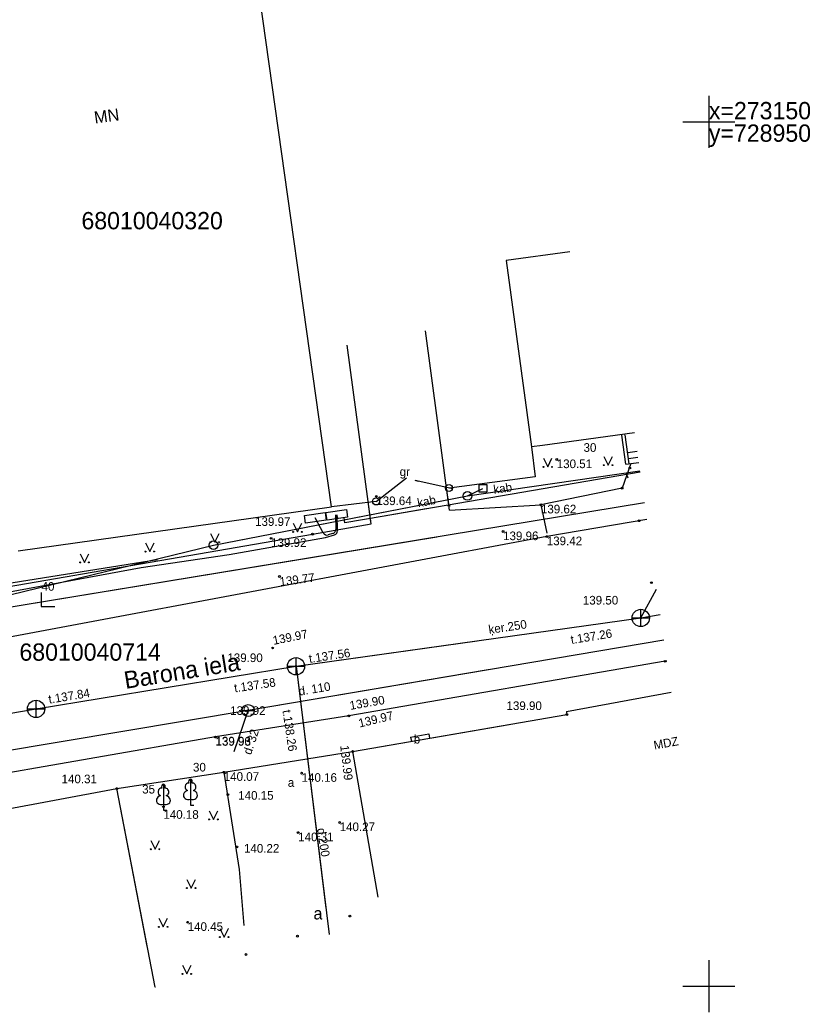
# Model space of a CAD drawing. Extents: x 728848 to 728956, y 273098 to 273185.
# Drawn here: x 728910.1 to 728955.9, y 273098.5 to 273155.9 of the extents above; entities that cross this region are included whole.
import ezdxf

# ---------------------------------------------------------------- set-up
doc = ezdxf.new("R2010")
doc.units = 0
for name, color, linetype in [('BUVE_BDET_####_####_#', 7, 'Continuous'), ('BUVE_BDET_####_TKST_#', 7, 'Continuous'), ('BUVE_EKAS_####_####_#', 7, 'Continuous'), ('BUVE_EKAS_RAKS_TKST_#', 7, 'Continuous'), ('CELI_CAPM_####_####_#', 7, 'Continuous'), ('CELI_CMAL_####_####_#', 7, 'Continuous'), ('CELI_CSEG_####_TKST_#', 7, 'Continuous'), ('CELI_IELA_####_TKST_#', 7, 'Continuous'), ('CELI_SEGL_####_####_#', 7, 'Continuous'), ('ELEK_ELEM_####_####_#', 7, 'Continuous'), ('ELEK_VADP_ZSPR_####_#', 7, 'Continuous'), ('ELEK_VADP_ZSPR_####_I', 7, 'Continuous'), ('ELEK_VADV_ZSPR_####_#', 7, 'Continuous'), ('ELEK_VADV_ZSPR_TKST_#', 7, 'Continuous'), ('GEOD_ELEM_####_####_#', 7, 'Continuous'), ('GEOD_KORD_####_TKST_#', 7, 'Continuous'), ('Level 1', 7, 'Continuous'), ('Level 23', 7, 'Continuous'), ('NORB_ELEM_####_####_#', 7, 'Continuous'), ('NORB_ZOGS_BARJ_####_#', 7, 'Continuous'), ('NORB_ZOGS_KOKA_####_#', 7, 'Continuous'), ('RELJ_AATZ_####_TKST_#', 7, 'Continuous'), ('RELJ_ELEM_####_####_#', 7, 'Continuous'), ('ROBZ_KADS_####_TKST_#', 7, 'Continuous'), ('ROBZ_UZMR_####_####_#', 7, 'Continuous'), ('SAKK_KKAN_####_####_#', 7, 'Continuous'), ('SKAN_ELEM_####_####_#', 7, 'Continuous'), ('SKAN_VADP_PAST_####_#', 7, 'Continuous'), ('SKAN_VADP_PAST_TKST_#', 7, 'Continuous'), ('TERT_ELEM_####_####_#', 7, 'Continuous'), ('UDTK_ELEM_####_####_#', 7, 'Continuous'), ('UDTK_ELEM_####_TKST_#', 7, 'Continuous'), ('UDTK_VADP_UDEN_####_#', 7, 'Continuous'), ('UDTK_VADP_UDEN_TKST_#', 7, 'Continuous')]:
    doc.layers.add(name, color=color, linetype=linetype)

msp = doc.modelspace()

# ---------------------------------------------------------------- linework, layer by layer
at = {"layer": 'BUVE_BDET_####_####_#'}
for p, q in [((728945.201, 273130.202), (728944.965, 273131.873)), ((728945.391, 273130.228), (728945.156, 273131.897)), ((728945.301, 273130.87), (728945.849, 273130.946)), ((728945.349, 273130.528), (728945.897, 273130.604)), ((728945.201, 273130.202), (728945.939, 273130.304)), ((728932.744, 273114.398), (728933.793, 273114.592)), ((728932.744, 273114.398), (728932.787, 273114.164)), ((728933.793, 273114.592), (728933.839, 273114.345))]:
    msp.add_line(p, q, dxfattribs=at)
at = {"layer": 'BUVE_EKAS_####_####_#'}
for p, q in [((728928.159, 273127.726), (728923.879, 273158.199)), ((728941.955, 273142.483), (728938.276, 273141.982)), ((728938.276, 273141.982), (728939.731, 273131.201)), ((728945.697, 273132.02), (728940.375, 273131.284)), ((728940.375, 273131.284), (728939.731, 273131.201)), ((728910.037, 273125.181), (728928.159, 273127.726)), ((728941.754, 273115.883), (728947.818, 273117.013)), ((728929.388, 273113.579), (728941.786, 273115.713)), ((728941.754, 273115.883), (728941.786, 273115.713)), ((728929.388, 273113.579), (728938.449, 273115.139)), ((728929.388, 273113.579), (728930.84, 273105.143)), ((728899.988, 273108.511), (728915.742, 273111.435)), ((728917.962, 273099.938), (728915.742, 273111.435)), ((728917.502, 273102.322), (728915.742, 273111.435))]:
    msp.add_line(p, q, dxfattribs=at)
at = {"layer": 'CELI_CAPM_####_####_#'}
msp.add_line((728947.564, 273118.811), (728947.473, 273118.795), dxfattribs=at)
for points in [[(728946.407, 273126.997), (728940.62, 273126.01)], [(728947.473, 273118.795), (728929.173, 273115.635), (728921.451, 273114.43)], [(728921.451, 273114.43), (728906.807, 273111.886), (728887.177, 273108.316), (728884.836, 273107.893)]]:
    msp.add_lwpolyline(points, dxfattribs=at)
at = {"layer": 'CELI_CMAL_####_####_#'}
for p, q in [((728934.999, 273127.535), (728933.598, 273137.914)), ((728930.461, 273126.743), (728929.065, 273137.091)), ((728934.964, 273127.794), (728934.862, 273128.552)), ((728930.444, 273126.872), (728930.308, 273127.882)), ((728905.649, 273122.465), (728927.067, 273126.15))]:
    msp.add_line(p, q, dxfattribs=at)
for points in [[(728945.475, 273130.229), (728944.976, 273128.81)], [(728945.222, 273129.688), (728945.313, 273129.411)], [(728944.976, 273128.81), (728940.282, 273127.851), (728940.62, 273126.21)], [(728934.999, 273127.535), (728940.282, 273127.851)], [(728927.067, 273126.15), (728930.461, 273126.743)], [(728940.62, 273126.01), (728905.191, 273119.377), (728883.236, 273115.671)], [(728915.742, 273111.435), (728921.935, 273112.38)], [(728921.935, 273112.38), (728922.812, 273106.757), (728923.087, 273103.503)]]:
    msp.add_lwpolyline(points, dxfattribs=at)
at = {"layer": 'CELI_SEGL_####_####_#'}
msp.add_lwpolyline([(728921.935, 273112.38), (728921.929, 273112.38), (728929.388, 273113.579)], dxfattribs=at)
at = {"layer": 'ELEK_ELEM_####_####_#'}
for points in [[(728937.145, 273128.578), (728936.699, 273128.578), (728936.699, 273129.018), (728937.145, 273129.018)], [(728927.838, 273127.406), (728929.025, 273127.586), (728929.092, 273127.141), (728927.906, 273126.961)], [(728926.603, 273127.239), (728927.793, 273127.398), (728927.853, 273126.952), (728926.663, 273126.793)]]:
    msp.add_lwpolyline(points, close=True, dxfattribs=at)
for centre in [(728936.036, 273128.36), (728921.335, 273125.511)]:
    msp.add_circle(centre, 0.25, dxfattribs=at)
at = {"layer": 'ELEK_VADP_ZSPR_####_#'}
for points in [[(728946.018, 273129.745), (728931.098, 273127.179), (728928.944, 273126.808), (728928.895, 273127.096)], [(728936.036, 273128.36), (728936.922, 273128.797)], [(728933.644, 273127.617), (728931.098, 273127.179), (728928.944, 273126.808), (728928.895, 273127.096)]]:
    msp.add_lwpolyline(points, dxfattribs=at)
at = {"layer": 'ELEK_VADP_ZSPR_####_I'}
for p, q in [((728928.389, 273127.266), (728928.409, 273126.427)), ((728928.511, 273126.353), (728928.489, 273127.268)), ((728928.511, 273126.353), (728928.489, 273127.268)), ((728927.817, 273125.955), (728928.332, 273126.107)), ((728927.817, 273125.955), (728928.332, 273126.107)), ((728928.23, 273126.181), (728927.976, 273126.106))]:
    msp.add_line(p, q, dxfattribs=at)
for points in [[(728927.684, 273126.23), (728927.228, 273127.096)], [(728882.763, 273118.325), (728887.201, 273119.02), (728893.506, 273120.092), (728901.17, 273121.265), (728917.144, 273124.228), (728922.252, 273124.972), (728927.817, 273125.955)], [(728884.14, 273118.541), (728887.201, 273119.02), (728893.506, 273120.092), (728901.17, 273121.265), (728917.144, 273124.228), (728922.252, 273124.972), (728927.817, 273125.955)]]:
    msp.add_lwpolyline(points, dxfattribs=at)
for centre, start, end in [((728928.159, 273126.421), 286.45134, 1.36735), ((728928.261, 273126.347), 286.45134, 1.36735), ((728928.261, 273126.347), 286.45134, 1.36735), ((728927.905, 273126.346), 207.75459, 286.45134)]:
    msp.add_arc(centre, 0.25, start, end, dxfattribs=at)
at = {"layer": 'ELEK_VADV_ZSPR_####_#'}
for p, q in [((728936.036, 273128.36), (728946.01, 273129.807)), ((728921.335, 273125.511), (728936.036, 273128.36)), ((728921.335, 273125.511), (728933.544, 273127.877)), ((728894.302, 273118.95), (728921.335, 273125.511))]:
    msp.add_line(p, q, dxfattribs=at)
at = {"layer": 'GEOD_ELEM_####_####_#'}
for p, q in [((728950, 273151.5), (728950, 273150)), ((728948.5, 273150), (728950, 273150)), ((728950, 273150), (728950, 273148.5)), ((728950, 273150), (728951.5, 273150)), ((728950, 273101.5), (728950, 273100)), ((728948.5, 273100), (728950, 273100)), ((728950, 273100), (728950, 273098.5)), ((728950, 273100), (728951.5, 273100))]:
    msp.add_line(p, q, dxfattribs=at)
at = {"layer": 'Level 1'}
for p, q in [((728911.357, 273122.769), (728911.357, 273121.969)), ((728911.357, 273121.969), (728912.157, 273121.969))]:
    msp.add_line(p, q, dxfattribs=at)
at = {"layer": 'Level 23'}
for p, q in [((728940.422, 273130.543), (728940.672, 273130.043)), ((728940.672, 273130.043), (728940.922, 273130.543)), ((728943.917, 273130.642), (728944.167, 273130.142)), ((728944.167, 273130.142), (728944.417, 273130.642))]:
    msp.add_line(p, q, dxfattribs=at)
for centre, radius in [((728940.422, 273130.042), 0.028), ((728940.922, 273130.042), 0.0263), ((728943.916, 273130.142), 0.028), ((728944.416, 273130.142), 0.0263)]:
    msp.add_circle(centre, radius, dxfattribs=at)
at = {"layer": 'NORB_ELEM_####_####_#'}
for centre in [(728934.964, 273128.82), (728930.745, 273128.042)]:
    msp.add_circle(centre, 0.202, dxfattribs=at)
at = {"layer": 'NORB_ZOGS_BARJ_####_#'}
for points in [[(728930.745, 273128.042), (728932.505, 273129.41)], [(728935.188, 273128.772), (728933.01, 273129.246)], [(728933.199, 273129.205), (728933.01, 273129.246)]]:
    msp.add_lwpolyline(points, dxfattribs=at)
at = {"layer": 'NORB_ZOGS_KOKA_####_#'}
msp.add_line((728930.745, 273128.042), (728928.159, 273127.726), dxfattribs=at)
msp.add_lwpolyline([(728939.731, 273131.201), (728939.949, 273129.466), (728934.964, 273128.82)], dxfattribs=at)
at = {"layer": 'RELJ_ELEM_####_####_#'}
for centre in [(728941.197, 273130.47), (728945.427, 273129.976), (728944.976, 273128.81), (728930.758, 273128.331), (728934.964, 273127.794), (728940.282, 273127.851), (728928.453, 273127.128), (728945.971, 273126.926), (728938.092, 273126.303), (728924.669, 273125.911), (728927.067, 273126.15), (728940.62, 273126.01), (728925.156, 273123.7), (728946.674, 273123.345), (728946.06, 273121.302), (728924.758, 273119.566), (728926.111, 273118.506), (728947.473, 273118.795), (728911.07, 273116.044), (728923.344, 273115.945), (728929.173, 273115.635), (728941.786, 273115.713), (728921.457, 273114.41), (728929.388, 273113.579), (728921.929, 273112.38), (728926.435, 273112.324), (728915.742, 273111.435), (728922.17, 273111.086), (728918.437, 273110.385), (728928.637, 273109.471), (728926.237, 273108.887), (728922.695, 273108.059), (728929.224, 273104.056), (728919.844, 273103.7), (728926.193, 273102.894), (728923.217, 273101.834)]:
    msp.add_circle(centre, 0.05, dxfattribs=at)
at = {"layer": 'ROBZ_UZMR_####_####_#'}
msp.add_lwpolyline([(728906.58, 273122.86), (728918.09, 273124.69)], dxfattribs=at)
at = {"layer": 'SAKK_KKAN_####_####_#'}
for points in [[(728882.864, 273117.761), (728887.446, 273118.532), (728897.906, 273120.141), (728908.778, 273121.814), (728946.269, 273127.973)], [(728884.177, 273117.982), (728887.446, 273118.532), (728897.906, 273120.141), (728908.778, 273121.814), (728934.266, 273126.001)]]:
    msp.add_lwpolyline(points, dxfattribs=at)
at = {"layer": 'SKAN_ELEM_####_####_#'}
for p, q in [((728946.06, 273120.802), (728946.06, 273121.802)), ((728945.56, 273121.302), (728946.56, 273121.302)), ((728926.111, 273118.006), (728926.111, 273119.006)), ((728925.611, 273118.506), (728926.611, 273118.506)), ((728910.57, 273116.044), (728911.57, 273116.044)), ((728911.07, 273115.544), (728911.07, 273116.544))]:
    msp.add_line(p, q, dxfattribs=at)
for centre in [(728946.06, 273121.302), (728926.111, 273118.506), (728911.07, 273116.044)]:
    msp.add_circle(centre, 0.5, dxfattribs=at)
at = {"layer": 'SKAN_VADP_PAST_####_#'}
for points in [[(728946.06, 273121.302), (728946.977, 273122.962)], [(728926.111, 273118.506), (728946.06, 273121.302), (728947.184, 273121.501)], [(728926.111, 273118.506), (728936.587, 273119.974)], [(728886.872, 273111.928), (728911.07, 273116.044), (728926.111, 273118.506), (728928.031, 273102.999)], [(728886.872, 273111.928), (728911.07, 273116.044), (728926.111, 273118.506), (728927.844, 273104.509)], [(728917.987, 273099.945), (728917.961, 273099.941)]]:
    msp.add_lwpolyline(points, dxfattribs=at)
at = {"layer": 'TERT_ELEM_####_####_#'}
for p, q in [((728925.943, 273126.781), (728926.193, 273126.281)), ((728926.193, 273126.281), (728926.443, 273126.781)), ((728921.159, 273126.188), (728921.409, 273125.688)), ((728921.409, 273125.688), (728921.659, 273126.188)), ((728917.397, 273125.646), (728917.647, 273125.146)), ((728917.647, 273125.146), (728917.897, 273125.646)), ((728913.624, 273125.017), (728913.874, 273124.517)), ((728913.874, 273124.517), (728914.124, 273125.017)), ((728918.437, 273110.532), (728918.437, 273110.185)), ((728920.004, 273110.828), (728920.004, 273110.481)), ((728920.004, 273110.481), (728920.204, 273110.481)), ((728918.437, 273110.185), (728918.637, 273110.185)), ((728921.084, 273110.152), (728921.334, 273109.652)), ((728921.334, 273109.652), (728921.584, 273110.152)), ((728917.703, 273108.423), (728917.953, 273107.923)), ((728917.953, 273107.923), (728918.203, 273108.423)), ((728919.798, 273106.179), (728920.048, 273105.679)), ((728920.048, 273105.679), (728920.298, 273106.179)), ((728918.18, 273103.934), (728918.43, 273103.434)), ((728918.43, 273103.434), (728918.68, 273103.934)), ((728921.709, 273103.346), (728921.959, 273102.846)), ((728921.709, 273103.346), (728921.77, 273103.224)), ((728921.959, 273102.846), (728922.209, 273103.346)), ((728922.193, 273103.314), (728922.209, 273103.346)), ((728919.54, 273101.212), (728919.79, 273100.712)), ((728919.79, 273100.712), (728920.04, 273101.212))]:
    msp.add_line(p, q, dxfattribs=at)
for points in [[(728918.437, 273111.685), (728918.437, 273110.532)], [(728918.527, 273111.453), (728918.526, 273111.454)], [(728920.004, 273111.981), (728920.004, 273110.828)], [(728920.094, 273111.749), (728920.093, 273111.75)]]:
    msp.add_lwpolyline(points, dxfattribs=at)
for centre, radius in [((728925.943, 273126.281), 0.028), ((728926.443, 273126.281), 0.0263), ((728921.158, 273125.688), 0.028), ((728921.658, 273125.688), 0.0263), ((728917.397, 273125.146), 0.028), ((728917.897, 273125.146), 0.0263), ((728913.624, 273124.516), 0.028), ((728914.124, 273124.516), 0.0263), ((728921.084, 273109.651), 0.028), ((728921.584, 273109.651), 0.0263), ((728917.702, 273107.922), 0.028), ((728918.202, 273107.922), 0.0263), ((728919.797, 273105.678), 0.028), ((728920.297, 273105.678), 0.0263), ((728918.18, 273103.434), 0.028), ((728918.68, 273103.434), 0.0263), ((728921.709, 273102.845), 0.028), ((728922.209, 273102.845), 0.0263), ((728919.54, 273100.711), 0.028), ((728920.04, 273100.711), 0.0263)]:
    msp.add_circle(centre, radius, dxfattribs=at)
for centre, major_axis, ratio, start_param, end_param in [((728918.309, 273111.24), (-0.039, -0.212), 0.861323, 3.141593, 6.283185), ((728918.437, 273111.535), (0, -0.15), 0.707107, 3.14537, 5.287485), ((728918.437, 273111.535), (0, -0.15), 0.707107, 0.995701, 3.137816), ((728918.565, 273111.24), (0.039, -0.212), 0.861323, 0, 3.141593), ((728919.876, 273111.537), (-0.039, -0.212), 0.861323, 3.141593, 6.283185), ((728920.004, 273111.832), (0, -0.15), 0.707107, 3.14537, 5.287485), ((728920.004, 273111.832), (0, -0.15), 0.707107, 0.995701, 3.137816), ((728920.132, 273111.537), (0.039, -0.212), 0.861323, 0, 3.141593), ((728918.347, 273110.778), (0.307, 0.095), 0.814445, 1.570796, 4.752015), ((728918.527, 273110.778), (-0.307, 0.095), 0.814445, 1.531171, 4.712389), ((728919.914, 273111.074), (0.307, 0.095), 0.814445, 1.570796, 4.752015), ((728920.094, 273111.074), (-0.307, 0.095), 0.814445, 1.531171, 4.712389)]:
    msp.add_ellipse(centre, major_axis=major_axis, ratio=ratio, start_param=start_param, end_param=end_param, dxfattribs=at)
at = {"layer": 'UDTK_ELEM_####_####_#'}
for p, q in [((728922.994, 273115.944), (728923.696, 273115.944)), ((728923.344, 273115.944), (728923.344, 273115.945))]:
    msp.add_line(p, q, dxfattribs=at)
msp.add_circle((728923.345, 273115.944), 0.351, dxfattribs=at)
at = {"layer": 'UDTK_VADP_UDEN_####_#'}
for p, q in [((728947.393, 273120.023), (728923.344, 273115.945)), ((728937.232, 273118.3), (728923.344, 273115.945)), ((728923.344, 273115.945), (728888.239, 273110.085)), ((728922.523, 273113.582), (728923.344, 273115.945))]:
    msp.add_line(p, q, dxfattribs=at)

# ---------------------------------------------------------------- texts
at = {"layer": 'BUVE_BDET_####_TKST_#'}
msp.add_text('b', height=0.5, dxfattribs=at).set_placement((728932.922, 273114.038))
at = {"layer": 'BUVE_EKAS_RAKS_TKST_#'}
for s, height, rotation, p in [('MN', 0.7, 7.80082, (728914.478, 273149.896)), ('MDZ', 0.5, 10.44819, (728946.852, 273113.686))]:
    msp.add_text(s, height=height, rotation=rotation, dxfattribs=at).set_placement(p)
at = {"layer": 'CELI_CSEG_####_TKST_#'}
for s, height, p in [('gr', 0.5, (728932.106, 273129.515)), ('a', 0.5, (728925.639, 273111.535)), ('a', 0.7, (728927.122, 273103.862))]:
    msp.add_text(s, height=height, dxfattribs=at).set_placement(p)
at = {"layer": 'CELI_IELA_####_TKST_#'}
msp.add_text('Barona iela', height=1, rotation=9.29607, dxfattribs=at).set_placement((728916.249, 273117.196))
at = {"layer": 'ELEK_VADV_ZSPR_TKST_#'}
for rotation, p in [(8.25832, (728937.571, 273128.481)), (10.96598, (728933.182, 273127.705))]:
    msp.add_text('kab', height=0.5, rotation=rotation, dxfattribs=at).set_placement(p)
at = {"layer": 'GEOD_KORD_####_TKST_#'}
for s, p in [('x=273150', (728950, 273150.15)), ('y=728950', (728950, 273148.85))]:
    msp.add_text(s, height=1, dxfattribs=at).set_placement(p)
at = {"layer": 'Level 1'}
for s, p in [('30', (728942.747, 273130.913)), ('40', (728911.388, 273122.876)), ('30', (728920.149, 273112.419)), ('35', (728917.21, 273111.147))]:
    msp.add_text(s, height=0.5, dxfattribs=at).set_placement(p)
at = {"layer": 'RELJ_AATZ_####_TKST_#'}
for s, p in [('130.51', (728941.197, 273129.97)), ('139.64', (728930.758, 273127.831)), ('139.62', (728940.282, 273127.351)), (' 139.97', (728923.557, 273126.626)), ('139.92', (728924.669, 273125.411)), ('139.96', (728938.092, 273125.803)), ('139.42', (728940.62, 273125.51)), (' 139.90', (728938.104, 273115.977)), ('139.96', (728921.451, 273113.93)), ('139.93', (728921.457, 273113.91)), (' 140.31', (728912.361, 273111.739)), ('140.07', (728921.929, 273111.88)), ('140.16', (728926.435, 273111.824)), ('140.15', (728922.767, 273110.788)), ('140.18', (728918.437, 273109.685)), ('140.27', (728928.637, 273108.971)), ('140.31', (728926.237, 273108.387)), ('140.22', (728923.101, 273107.725)), ('140.45', (728919.844, 273103.2))]:
    msp.add_text(s, height=0.5, dxfattribs=at).set_placement(p)
for s, rotation, p in [('139.77', 7.25042, (728925.191, 273123.146)), ('139.97', 11.31902, (728924.818, 273119.746)), ('139.90', 9.76585, (728929.257, 273115.983)), ('139.97', 13.40314, (728929.79, 273114.962)), (' 139.99', 276.7684, (728928.642, 273114.099))]:
    msp.add_text(s, height=0.5, rotation=rotation, dxfattribs=at).set_placement(p)
at = {"layer": 'ROBZ_KADS_####_TKST_#'}
for s, p in [('68010040320', (728913.695, 273143.786)), ('68010040714', (728910.107, 273118.83))]:
    msp.add_text(s, height=1, dxfattribs=at).set_placement(p)
at = {"layer": 'SKAN_ELEM_####_####_#'}
for s, p in [('139.50', (728942.708, 273122.079)), ('139.90', (728922.14, 273118.751))]:
    msp.add_text(s, height=0.5, dxfattribs=at).set_placement(p)
at = {"layer": 'SKAN_VADP_PAST_TKST_#'}
for s, rotation, p in [('ķer.250', 8.499, (728937.289, 273120.377)), ('t.137.26', 9.174, (728942.047, 273119.793)), ('t.137.56', 8.499, (728926.893, 273118.695)), ('t.137.58', 8.499, (728922.571, 273116.992)), ('t.137.84', 9.41, (728911.832, 273116.342)), ('t.138.26', 278.559, (728925.323, 273115.948)), ('d.200', 278.559, (728927.328, 273109.113))]:
    msp.add_text(s, height=0.5, rotation=rotation, dxfattribs=at).set_placement(p)
at = {"layer": 'UDTK_ELEM_####_TKST_#'}
msp.add_text('139.92', height=0.5, dxfattribs=at).set_placement((728922.302, 273115.695))
at = {"layer": 'UDTK_VADP_UDEN_TKST_#'}
for s, rotation, p in [('d. 110', 9.45018, (728926.304, 273116.809)), ('d. 32', 71.668, (728923.506, 273113.353))]:
    msp.add_text(s, height=0.5, rotation=rotation, dxfattribs=at).set_placement(p)

doc.saveas('drawing.dxf')
